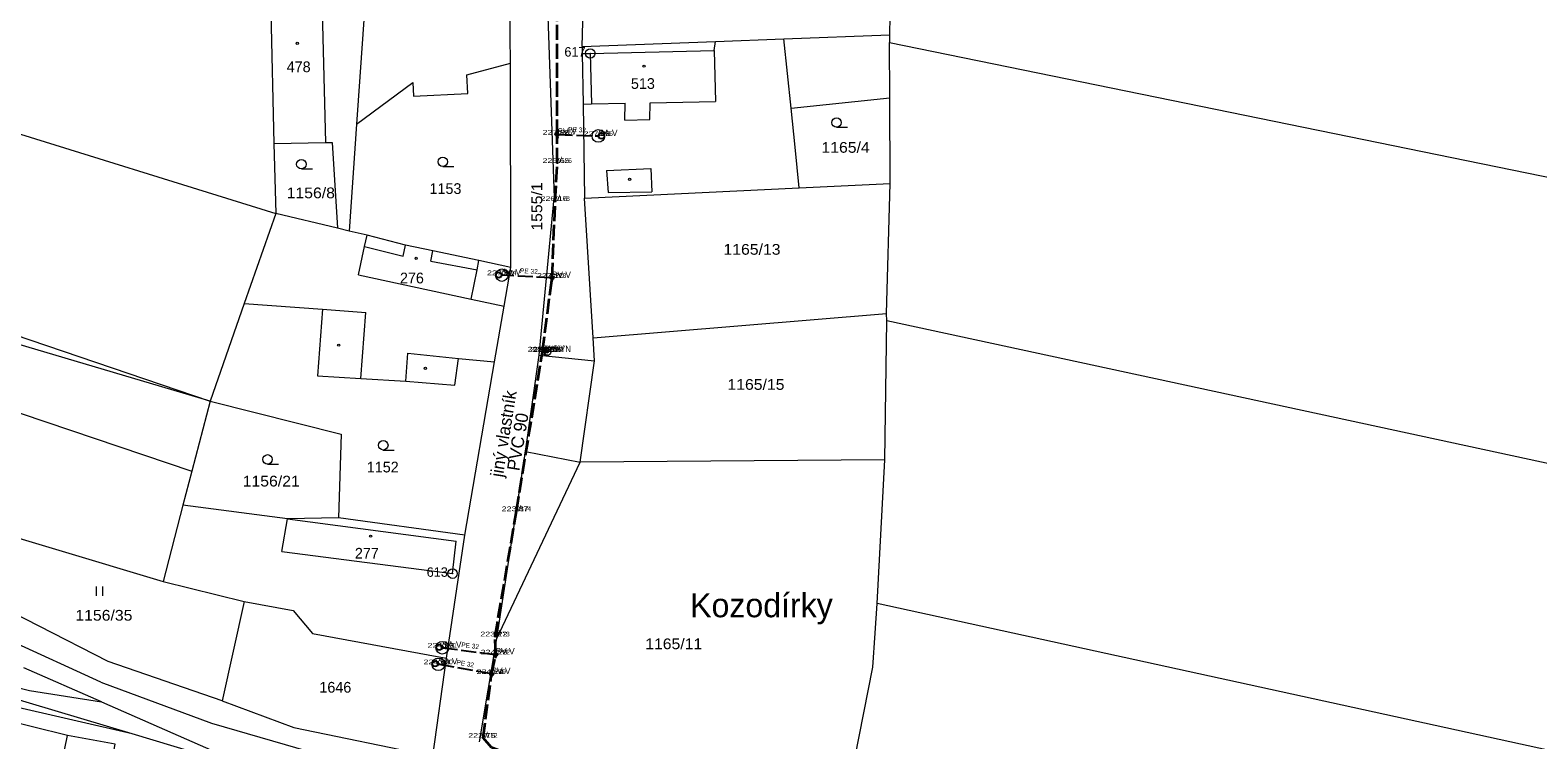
# Model space of a CAD drawing. Extents: x -686207 to -681951, y -1020493 to -1017811.
# Drawn here: x -684334 to -684095.1, y -1019178.1 to -1019065.6 of the extents above; entities that cross this region are included whole.
import ezdxf
from ezdxf.enums import TextEntityAlignment as Align

# ---------------------------------------------------------------- set-up
doc = ezdxf.new("R2010")
doc.units = 0
doc.header["$LTSCALE"] = 0.4
doc.header["$PDMODE"] = 32
doc.header["$PDSIZE"] = 0.2
doc.linetypes.add('DOTTED', pattern=[1.5, 0.3, -1.2])
doc.linetypes.add('LONG_DASHED', pattern=[7.5, 6, -1.5])
for name, color, linetype, lineweight in [('1', 7, 'Continuous', 13), ('10', 7, 'Continuous', 13), ('12', 7, 'Continuous', 13), ('3', 7, 'Continuous', 13), ('35', 7, 'LONG_DASHED', 35), ('4', 7, 'Continuous', 13), ('5', 7, 'Continuous', 13), ('50', 7, 'LONG_DASHED', 25), ('51', 7, 'DOTTED', 25), ('6', 7, 'Continuous', 13), ('7', 7, 'Continuous', 13), ('8', 7, 'Continuous', 13)]:
    doc.layers.add(name, color=color, linetype=linetype, lineweight=lineweight)
for name, color, linetype in [('17', 7, 'Continuous'), ('19', 7, 'Continuous'), ('2', 7, 'Continuous')]:
    doc.layers.add(name, color=color, linetype=linetype)

msp = doc.modelspace()

# ---------------------------------------------------------------- linework, layer by layer
at = {"layer": '1'}
for p, q in [((-684197.36, -1019041.02), (-684197.86, -1019066.35)), ((-684246.54, -1019068.23), (-684245.95, -1019044.93)), ((-684295.88, -1019062.8), (-684295.43, -1019083.6)), ((-684281.03, -1019062.49), (-684282.28, -1019080.53)), ((-684214.59, -1019067), (-684197.86, -1019066.35)), ((-684197.86, -1019066.35), (-684197.85, -1019067.57)), ((-684197.85, -1019067.57), (-683965.52, -1019115.17)), ((-684257.84, -1019103.22), (-684257.93, -1019070.84)), ((-684282.28, -1019080.53), (-684283.45, -1019097.46)), ((-684295.43, -1019083.6), (-684287.21, -1019083.44)), ((-684407.52, -1019089.82), (-684305.48, -1019124.42)), ((-684246.19, -1019092.25), (-684212.16, -1019090.63)), ((-684212.16, -1019090.63), (-684197.73, -1019089.95)), ((-684198.31, -1019110.52), (-684197.73, -1019089.95)), ((-684244.83, -1019114.38), (-684246.19, -1019092.25)), ((-684285.31, -1019097.02), (-684295.11, -1019094.7)), ((-684283.45, -1019097.46), (-684285.31, -1019097.02)), ((-684413.75, -1019099.84), (-684308.39, -1019135.53)), ((-684300.08, -1019108.94), (-684305.48, -1019124.42)), ((-684244.83, -1019114.38), (-684198.31, -1019110.52)), ((-684198.57, -1019133.71), (-684198.29, -1019111.69)), ((-684198.29, -1019111.69), (-684198.31, -1019110.52)), ((-683966.09, -1019161.81), (-684198.29, -1019111.69)), ((-684265.15, -1019145.65), (-684260.43, -1019118.21)), ((-684305.48, -1019124.42), (-684308.39, -1019135.53)), ((-684198.57, -1019133.71), (-684246.85, -1019134.12)), ((-684199.82, -1019156.49), (-684198.57, -1019133.71)), ((-684308.39, -1019135.53), (-684309.8, -1019140.92)), ((-684309.8, -1019140.92), (-684312.94, -1019152.98)), ((-684265.15, -1019145.65), (-684285.16, -1019142.94)), ((-684268.07, -1019165.17), (-684265.15, -1019145.65)), ((-684312.94, -1019152.98), (-684300.11, -1019156.17)), ((-684300.11, -1019156.17), (-684303.6, -1019171.9)), ((-684084.87, -1019181.63), (-684199.82, -1019156.49)), ((-684328.11, -1019177.42), (-684388.16, -1019162.63)), ((-684322.71, -1019172.07), (-684335, -1019166.67)), ((-684270.21, -1019180.68), (-684268.07, -1019165.17)), ((-684322.71, -1019172.07), (-684296.61, -1019183.52)), ((-684333.66, -1019204.71), (-684328.11, -1019177.42)), ((-684296.61, -1019183.52), (-684317.84, -1019177.17))]:
    msp.add_line(p, q, dxfattribs=at)
for points in [[(-684441.55, -1019031.19), (-684397.84, -1019057.1), (-684390.29, -1019060.49), (-684362.1, -1019072.92), (-684341.05, -1019080.4), (-684295.11, -1019094.7)], [(-684257.93, -1019070.84), (-684257.94, -1019066.54), (-684257.97, -1019054.54)], [(-684246.54, -1019068.23), (-684225.42, -1019067.43), (-684214.59, -1019067)], [(-684212.16, -1019090.63), (-684212.82, -1019084.17), (-684213.46, -1019077.97), (-684214.59, -1019067)], [(-684246.54, -1019068.23), (-684246.53, -1019069.35), (-684246.41, -1019077.34), (-684246.19, -1019092.25)], [(-684197.73, -1019089.95), (-684197.81, -1019076.33), (-684197.85, -1019067.57)], [(-684282.28, -1019080.53), (-684273.37, -1019073.9), (-684273.28, -1019076.08), (-684264.69, -1019075.69), (-684264.81, -1019072.73), (-684257.93, -1019070.84)], [(-684295.43, -1019083.6), (-684295.11, -1019094.7), (-684300.08, -1019108.94)], [(-684287.21, -1019083.44), (-684286.16, -1019083.42), (-684285.31, -1019097.02)], [(-684305.48, -1019124.42), (-684360.57, -1019108.08), (-684407.52, -1019089.82)], [(-684257.84, -1019103.22), (-684262.92, -1019102.15), (-684270.21, -1019100.61), (-684274.56, -1019099.73), (-684280.61, -1019098.13), (-684283.45, -1019097.46)], [(-684260.43, -1019118.21), (-684258.91, -1019109.39), (-684257.84, -1019103.22)], [(-684535.89, -1019106.84), (-684509.81, -1019108.98), (-684375.93, -1019158.85), (-684362, -1019163.25), (-684334.13, -1019170.3), (-684322.71, -1019172.07)], [(-684300.08, -1019108.94), (-684287.69, -1019109.87), (-684288.51, -1019120.39), (-684281.62, -1019120.85), (-684274.47, -1019121.27), (-684266.71, -1019121.87), (-684266.16, -1019117.64), (-684260.43, -1019118.21)], [(-684317.84, -1019177.17), (-684358.07, -1019165.14), (-684383.26, -1019157.13), (-684507.56, -1019111.25)], [(-684317.84, -1019177.17), (-684347.48, -1019170.32), (-684381.05, -1019159.79), (-684480.46, -1019122.98), (-684507.56, -1019111.25)], [(-684246.85, -1019134.12), (-684244.61, -1019118.02), (-684244.83, -1019114.38)], [(-684305.48, -1019124.42), (-684284.75, -1019129.68), (-684285.16, -1019142.94)], [(-684378.53, -1019131.6), (-684347.63, -1019142.59), (-684312.94, -1019152.98)], [(-684303.6, -1019171.9), (-684321.66, -1019165.69), (-684354.48, -1019148.86), (-684378.53, -1019131.6)], [(-684262.82, -1019178.4), (-684260.07, -1019162.03), (-684255.51, -1019132.38), (-684246.85, -1019134.12)], [(-684285.16, -1019142.94), (-684293.25, -1019143.1), (-684309.8, -1019140.92)], [(-684300.11, -1019156.17), (-684292.32, -1019157.6), (-684289.3, -1019161.26), (-684268.93, -1019165.01), (-684268.07, -1019165.17)], [(-684205.44, -1019191.78), (-684200.51, -1019166.6), (-684200.14, -1019161.17), (-684199.82, -1019156.49)], [(-684303.6, -1019171.9), (-684292.25, -1019176.13), (-684270.21, -1019180.68)], [(-684319.52, -1019194.14), (-684323.36, -1019193.35), (-684320.56, -1019178.77), (-684328.11, -1019177.42)]]:
    msp.add_lwpolyline(points, dxfattribs=at)
for p in [(-684250.47, -1019082.19), (-684243.99, -1019082.4), (-684250.49, -1019086.67), (-684250.81, -1019092.7), (-684259.28, -1019104.46), (-684251.37, -1019104.89), (-684252.84, -1019116.56), (-684252.49, -1019116.6), (-684252.02, -1019116.65), (-684256.96, -1019141.86), (-684260.34, -1019161.71), (-684268.71, -1019163.5), (-684260.29, -1019164.57), (-684269.35, -1019166.13), (-684260.94, -1019167.66), (-684262.26, -1019177.78)]:
    msp.add_point(p, dxfattribs=at)
at = {"layer": '10'}
for p, q in [((-684252.37, -1019115.85), (-684251.67, -1019115.85)), ((-684252.02, -1019116.15), (-684252.02, -1019115.85))]:
    msp.add_line(p, q, dxfattribs=at)
for points in [[(-684250.32, -1019082.69), (-684250.62, -1019081.69), (-684250.32, -1019081.69), (-684250.62, -1019082.69)], [(-684251.22, -1019105.39), (-684251.52, -1019104.39), (-684251.22, -1019104.39), (-684251.52, -1019105.39)], [(-684252.34, -1019117.1), (-684252.64, -1019116.1), (-684252.34, -1019116.1), (-684252.64, -1019117.1)], [(-684260.14, -1019165.07), (-684260.44, -1019164.07), (-684260.14, -1019164.07), (-684260.44, -1019165.07)], [(-684260.79, -1019168.16), (-684261.09, -1019167.16), (-684260.79, -1019167.16), (-684261.09, -1019168.16)]]:
    msp.add_lwpolyline(points, close=True, dxfattribs=at)
for centre, radius in [((-684243.99, -1019082.4), 1), ((-684259.28, -1019104.46), 1), ((-684252.02, -1019116.65), 0.5), ((-684268.71, -1019163.5), 1), ((-684269.35, -1019166.13), 1)]:
    msp.add_circle(centre, radius, dxfattribs=at)
at = {"layer": '12'}
for centre, radius in [((-684250.52, -1019082.188), 0.3), ((-684250.52, -1019082.188), 0.2), ((-684250.52, -1019082.188), 0.1), ((-684243.49, -1019082.416), 0.5), ((-684243.49, -1019082.416), 0.4), ((-684259.779, -1019104.433), 0.5), ((-684259.779, -1019104.433), 0.4), ((-684251.32, -1019104.893), 0.3), ((-684251.32, -1019104.893), 0.2), ((-684251.32, -1019104.893), 0.1), ((-684252.84, -1019116.56), 0.15), ((-684252.84, -1019116.56), 0.075), ((-684269.206, -1019163.437), 0.5), ((-684269.206, -1019163.437), 0.4), ((-684260.24, -1019164.576), 0.3), ((-684260.24, -1019164.576), 0.2), ((-684260.24, -1019164.576), 0.1), ((-684269.842, -1019166.041), 0.5), ((-684269.842, -1019166.041), 0.4), ((-684260.891, -1019167.669), 0.3), ((-684260.891, -1019167.669), 0.2), ((-684260.891, -1019167.669), 0.1)]:
    msp.add_circle(centre, radius, dxfattribs=at)
at = {"layer": '3'}
for p, q in [((-684206.243, -1019081.02), (-684204.493, -1019081.02)), ((-684291.043, -1019087.63), (-684289.293, -1019087.63)), ((-684268.633, -1019087.24), (-684266.883, -1019087.24)), ((-684278.063, -1019132.17), (-684276.313, -1019132.17)), ((-684296.393, -1019134.4), (-684294.643, -1019134.4)), ((-684323.481, -1019155.29), (-684323.481, -1019153.79)), ((-684322.48, -1019155.29), (-684322.48, -1019153.79))]:
    msp.add_line(p, q, dxfattribs=at)
for centre in [(-684206.2429, -1019080.2698), (-684291.0429, -1019086.8798), (-684268.6329, -1019086.4898), (-684278.0629, -1019131.4198), (-684296.3929, -1019133.6498)]:
    msp.add_circle(centre, 0.75, dxfattribs=at)
at = {"layer": '35'}
for p, q in [((-684252.84, -1019116.56), (-684251.32, -1019104.893)), ((-684252.84, -1019116.56), (-684252.49, -1019116.6)), ((-684252.49, -1019116.6), (-684252.02, -1019116.65)), ((-684260.891, -1019167.669), (-684260.24, -1019164.576))]:
    msp.add_line(p, q, dxfattribs=at)
for points in [[(-684250.52, -1019082.188), (-684250.5, -1019062.7), (-684250.68, -1019054.851)], [(-684251.32, -1019104.893), (-684250.81, -1019092.7), (-684250.49, -1019086.67), (-684250.52, -1019082.188)], [(-684260.24, -1019164.576), (-684260.34, -1019161.71), (-684256.96, -1019141.86), (-684252.84, -1019116.56)], [(-684258.35, -1019180.28), (-684258.71, -1019180.16), (-684260.94, -1019179.32), (-684262.26, -1019177.78), (-684260.891, -1019167.669)]]:
    msp.add_lwpolyline(points, dxfattribs=at)
at = {"layer": '4'}
for p, q in [((-684255.27, -1018972.28), (-684250.96, -1019092.18)), ((-684287.75, -1019062.66), (-684287.21, -1019083.44)), ((-684246.53, -1019069.35), (-684245.26, -1019069.32)), ((-684245.26, -1019069.32), (-684225.64, -1019068.88)), ((-684245.26, -1019069.32), (-684245.06, -1019077.32)), ((-684225.64, -1019068.88), (-684225.42, -1019067.43)), ((-684225.64, -1019068.88), (-684225.42, -1019076.95)), ((-684213.46, -1019077.97), (-684197.81, -1019076.33)), ((-684239.8, -1019079.87), (-684239.72, -1019077.22)), ((-684235.81, -1019079.8), (-684235.76, -1019077.15)), ((-684235.76, -1019077.15), (-684225.42, -1019076.95)), ((-684239.8, -1019079.87), (-684235.81, -1019079.8)), ((-684242.67, -1019087.87), (-684235.69, -1019087.54)), ((-684235.69, -1019087.54), (-684235.52, -1019091.23)), ((-684281.05, -1019099.93), (-684280.61, -1019098.13)), ((-684274.9, -1019101.43), (-684274.56, -1019099.73)), ((-684270.55, -1019102.26), (-684270.21, -1019100.61)), ((-684270.55, -1019102.26), (-684263.21, -1019103.61)), ((-684263.21, -1019103.61), (-684262.92, -1019102.15)), ((-684281.98, -1019104.41), (-684264.14, -1019108.26)), ((-684264.14, -1019108.26), (-684263.21, -1019103.61)), ((-684287.69, -1019109.87), (-684280.82, -1019110.38)), ((-684264.14, -1019108.26), (-684258.91, -1019109.39)), ((-684281.62, -1019120.85), (-684280.82, -1019110.38)), ((-684253.36, -1019117.14), (-684244.61, -1019118.02)), ((-684260.07, -1019162.03), (-684246.85, -1019134.12)), ((-684294.12, -1019148.27), (-684293.25, -1019143.1)), ((-684293.25, -1019143.1), (-684266.53, -1019146.61)), ((-684267.08, -1019151.76), (-684266.53, -1019146.61)), ((-684294.12, -1019148.27), (-684267.08, -1019151.76))]:
    msp.add_line(p, q, dxfattribs=at)
for points in [[(-684246.41, -1019077.34), (-684245.06, -1019077.32), (-684239.72, -1019077.22)], [(-684242.67, -1019087.87), (-684242.44, -1019091.38), (-684235.52, -1019091.23)], [(-684255.51, -1019132.38), (-684253.36, -1019117.14), (-684250.96, -1019092.18)], [(-684281.98, -1019104.41), (-684281.05, -1019099.93), (-684274.9, -1019101.43)], [(-684274.47, -1019121.27), (-684274.15, -1019116.84), (-684266.16, -1019117.64)]]:
    msp.add_lwpolyline(points, dxfattribs=at)
at = {"layer": '5'}
for centre in [(-684291.6868, -1019067.7192), (-684236.7368, -1019071.3392), (-684239.0268, -1019089.2692), (-684272.8468, -1019101.7892), (-684285.1268, -1019115.5492), (-684271.3968, -1019119.2292), (-684280.0768, -1019145.8192)]:
    msp.add_circle(centre, 0.175, dxfattribs=at)
at = {"layer": '50'}
for p, q in [((-684250.52, -1019082.188), (-684250.47, -1019082.19)), ((-684250.47, -1019082.19), (-684243.99, -1019082.4)), ((-684251.37, -1019104.89), (-684259.28, -1019104.46)), ((-684251.32, -1019104.893), (-684251.37, -1019104.89)), ((-684268.71, -1019163.5), (-684260.29, -1019164.57)), ((-684260.29, -1019164.57), (-684260.24, -1019164.576)), ((-684260.94, -1019167.66), (-684269.35, -1019166.13)), ((-684260.891, -1019167.669), (-684260.94, -1019167.66))]:
    msp.add_line(p, q, dxfattribs=at)
at = {"layer": '51'}
for p, q in [((-684243.99, -1019082.4), (-684243.49, -1019082.416)), ((-684259.28, -1019104.46), (-684259.779, -1019104.433)), ((-684268.71, -1019163.5), (-684269.206, -1019163.437)), ((-684269.35, -1019166.13), (-684269.842, -1019166.041))]:
    msp.add_line(p, q, dxfattribs=at)
at = {"layer": '6'}
for p, q in [((-684322.79, -1019168.97), (-684337.35, -1019162.32)), ((-684322.79, -1019168.97), (-684305.27, -1019175.44)), ((-684305.27, -1019175.44), (-684287.96, -1019180.46))]:
    msp.add_line(p, q, dxfattribs=at)
at = {"layer": '8'}
for centre, radius in [((-684245.26, -1019069.3198), 0.75), ((-684245.26, -1019069.3198), 0.03), ((-684267.08, -1019151.7598), 0.75), ((-684267.08, -1019151.7598), 0.03)]:
    msp.add_circle(centre, radius, dxfattribs=at)

# ---------------------------------------------------------------- texts
at = {"layer": '17'}
for s, p in [('jiný vlastník', (-684258.0269, -1019129.7457)), ('PVC 90', (-684255.7678, -1019131.0267))]:
    msp.add_text(s, height=2, rotation=80.751, dxfattribs=at).set_placement(p, align=Align.CENTER)
at = {"layer": '19'}
for rotation, p in [(358.144, (-684247.3681, -1019081.7896)), (356.888, (-684255.0069, -1019104.1923)), (352.758, (-684264.3368, -1019163.5523)), (349.689, (-684265.1361, -1019166.3878))]:
    msp.add_text('PE 32', height=0.75, rotation=rotation, dxfattribs=at).set_placement(p, align=Align.CENTER)
at = {"layer": '2'}
for s, height, p in [('478', 1.7, (-684293.37, -1019072.289)), ('513', 1.7, (-684238.824, -1019074.94)), ('0225', 0.75, (-684250.47, -1019082.19)), ('0226', 0.75, (-684243.99, -1019082.4)), ('0126', 0.75, (-684250.49, -1019086.67)), ('1153', 1.7, (-684270.737, -1019091.59)), ('0178', 0.75, (-684250.81, -1019092.7)), ('276', 1.7, (-684275.424, -1019105.76)), ('0224', 0.75, (-684259.28, -1019104.46)), ('0223', 0.75, (-684251.37, -1019104.89)), ('0175', 0.75, (-684252.84, -1019116.56)), ('0176', 0.75, (-684252.49, -1019116.6)), ('0177', 0.75, (-684252.02, -1019116.65)), ('1152', 1.7, (-684280.677, -1019135.72)), ('0174', 0.75, (-684256.96, -1019141.86)), ('277', 1.7, (-684282.564, -1019149.38)), ('0173', 0.75, (-684260.34, -1019161.71)), ('0221', 0.75, (-684268.71, -1019163.5)), ('0222', 0.75, (-684260.29, -1019164.57)), ('0220', 0.75, (-684269.35, -1019166.13)), ('0219', 0.75, (-684260.94, -1019167.66)), ('1646', 1.7, (-684288.187, -1019170.62)), ('0172', 0.75, (-684262.26, -1019177.78))]:
    msp.add_text(s, height=height, dxfattribs=at).set_placement(p)
at = {"layer": '2', "width": 1.1}
for s, p in [('1165/4', (-684208.635, -1019085.059)), ('1156/8', (-684293.37, -1019092.27)), ('1165/13', (-684224.16, -1019101.22)), ('1165/15', (-684223.53, -1019122.63)), ('1156/21', (-684300.338, -1019137.95)), ('1156/35', (-684326.85, -1019159.21)), ('1165/11', (-684236.56, -1019163.73))]:
    msp.add_text(s, height=1.7, dxfattribs=at).set_placement(p)
msp.add_text('1555/1', height=1.7, rotation=90, dxfattribs=at).set_placement((-684252.88, -1019097.405))
at = {"layer": '3', "width": 1.4}
for s, p in [('227 99 ', (-684250.47, -1019082.19)), ('227 98 ', (-684243.99, -1019082.4)), ('226 65 ', (-684250.49, -1019086.67)), ('226 16 ', (-684250.81, -1019092.7)), ('227 40 ', (-684259.28, -1019104.46)), ('227 10 ', (-684251.37, -1019104.89)), ('225 05 ', (-684252.84, -1019116.56)), ('226 66 ', (-684252.49, -1019116.6)), ('226 52 ', (-684252.02, -1019116.65)), ('223 87 ', (-684256.96, -1019141.86)), ('223 22 ', (-684260.34, -1019161.71)), ('224 83 ', (-684268.71, -1019163.5)), ('224 79 ', (-684260.29, -1019164.57)), ('224 43 ', (-684269.35, -1019166.13)), ('224 74 ', (-684260.94, -1019167.66)), ('222 75 ', (-684262.26, -1019177.78))]:
    msp.add_text(s, height=0.75, dxfattribs=at).set_placement(p, align=Align.CENTER)
at = {"layer": '4'}
for s, p in [('SV V', (-684250.47, -1019082.19)), ('SA V', (-684243.99, -1019082.4)), ('SA V', (-684259.28, -1019104.46)), ('SV V', (-684251.37, -1019104.89)), ('V SV', (-684252.49, -1019116.6)), ('SA V', (-684268.71, -1019163.5)), ('SV V', (-684260.29, -1019164.57)), ('SA V', (-684269.35, -1019166.13)), ('SV V', (-684260.94, -1019167.66))]:
    msp.add_text(s, height=1, dxfattribs=at).set_placement(p)
for s, width, p in [('V', 0.85, (-684250.49, -1019086.67)), ('V', 0.85, (-684250.81, -1019092.7)), ('V', 0.85, (-684252.84, -1019116.56)), ('V HYN', 0.9, (-684252.02, -1019116.65)), ('V', 0.85, (-684256.96, -1019141.86)), ('V', 0.85, (-684260.34, -1019161.71)), ('V', 0.85, (-684262.26, -1019177.78))]:
    msp.add_text(s, height=1, dxfattribs=dict(at, width=width)).set_placement(p)
at = {"layer": '7'}
msp.add_text('Kozodírky', height=3.8, dxfattribs=at).set_placement((-684229.44, -1019158.67))
at = {"layer": '8'}
for s, p in [('617', (-684249.363, -1019069.82)), ('613', (-684271.183, -1019152.26))]:
    msp.add_text(s, height=1.5, dxfattribs=at).set_placement(p)

doc.saveas('drawing.dxf')
